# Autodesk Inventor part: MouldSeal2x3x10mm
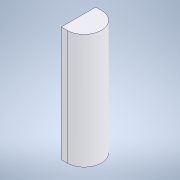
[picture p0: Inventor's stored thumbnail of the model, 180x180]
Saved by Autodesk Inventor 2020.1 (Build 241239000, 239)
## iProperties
Created: 2021-11
Part Number: MouldSeal2x3x10mm
Material: Generic
Document SubType Name: Modeling
Designer: c14576jb
Density: 1 g/cm^3
Appearance: Default
Author: c14576jb
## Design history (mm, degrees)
sketch "Sketch1"
  geometry: L1 (0, 0)-(2, 0); L2 (2, 0)-(2, -3); L3 (2, -3)-(0, -3); L4 (0, -3)-(0, 0)
  constraints: 8 end point, 2 parallel, 1 horizontal, 1 perpendicular
  dimensions: "d0" = 2 distance of L2.end L3.end; "d1" = 3 distance of L1.end L2.end
extrude "Extrusion1" new body sketch "Sketch1" distance "d2" = 10; taper "d3" = 0 deg
fillet "Fillet1"
body "Solid1"
